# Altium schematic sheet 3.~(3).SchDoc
size 420 x 297 mm
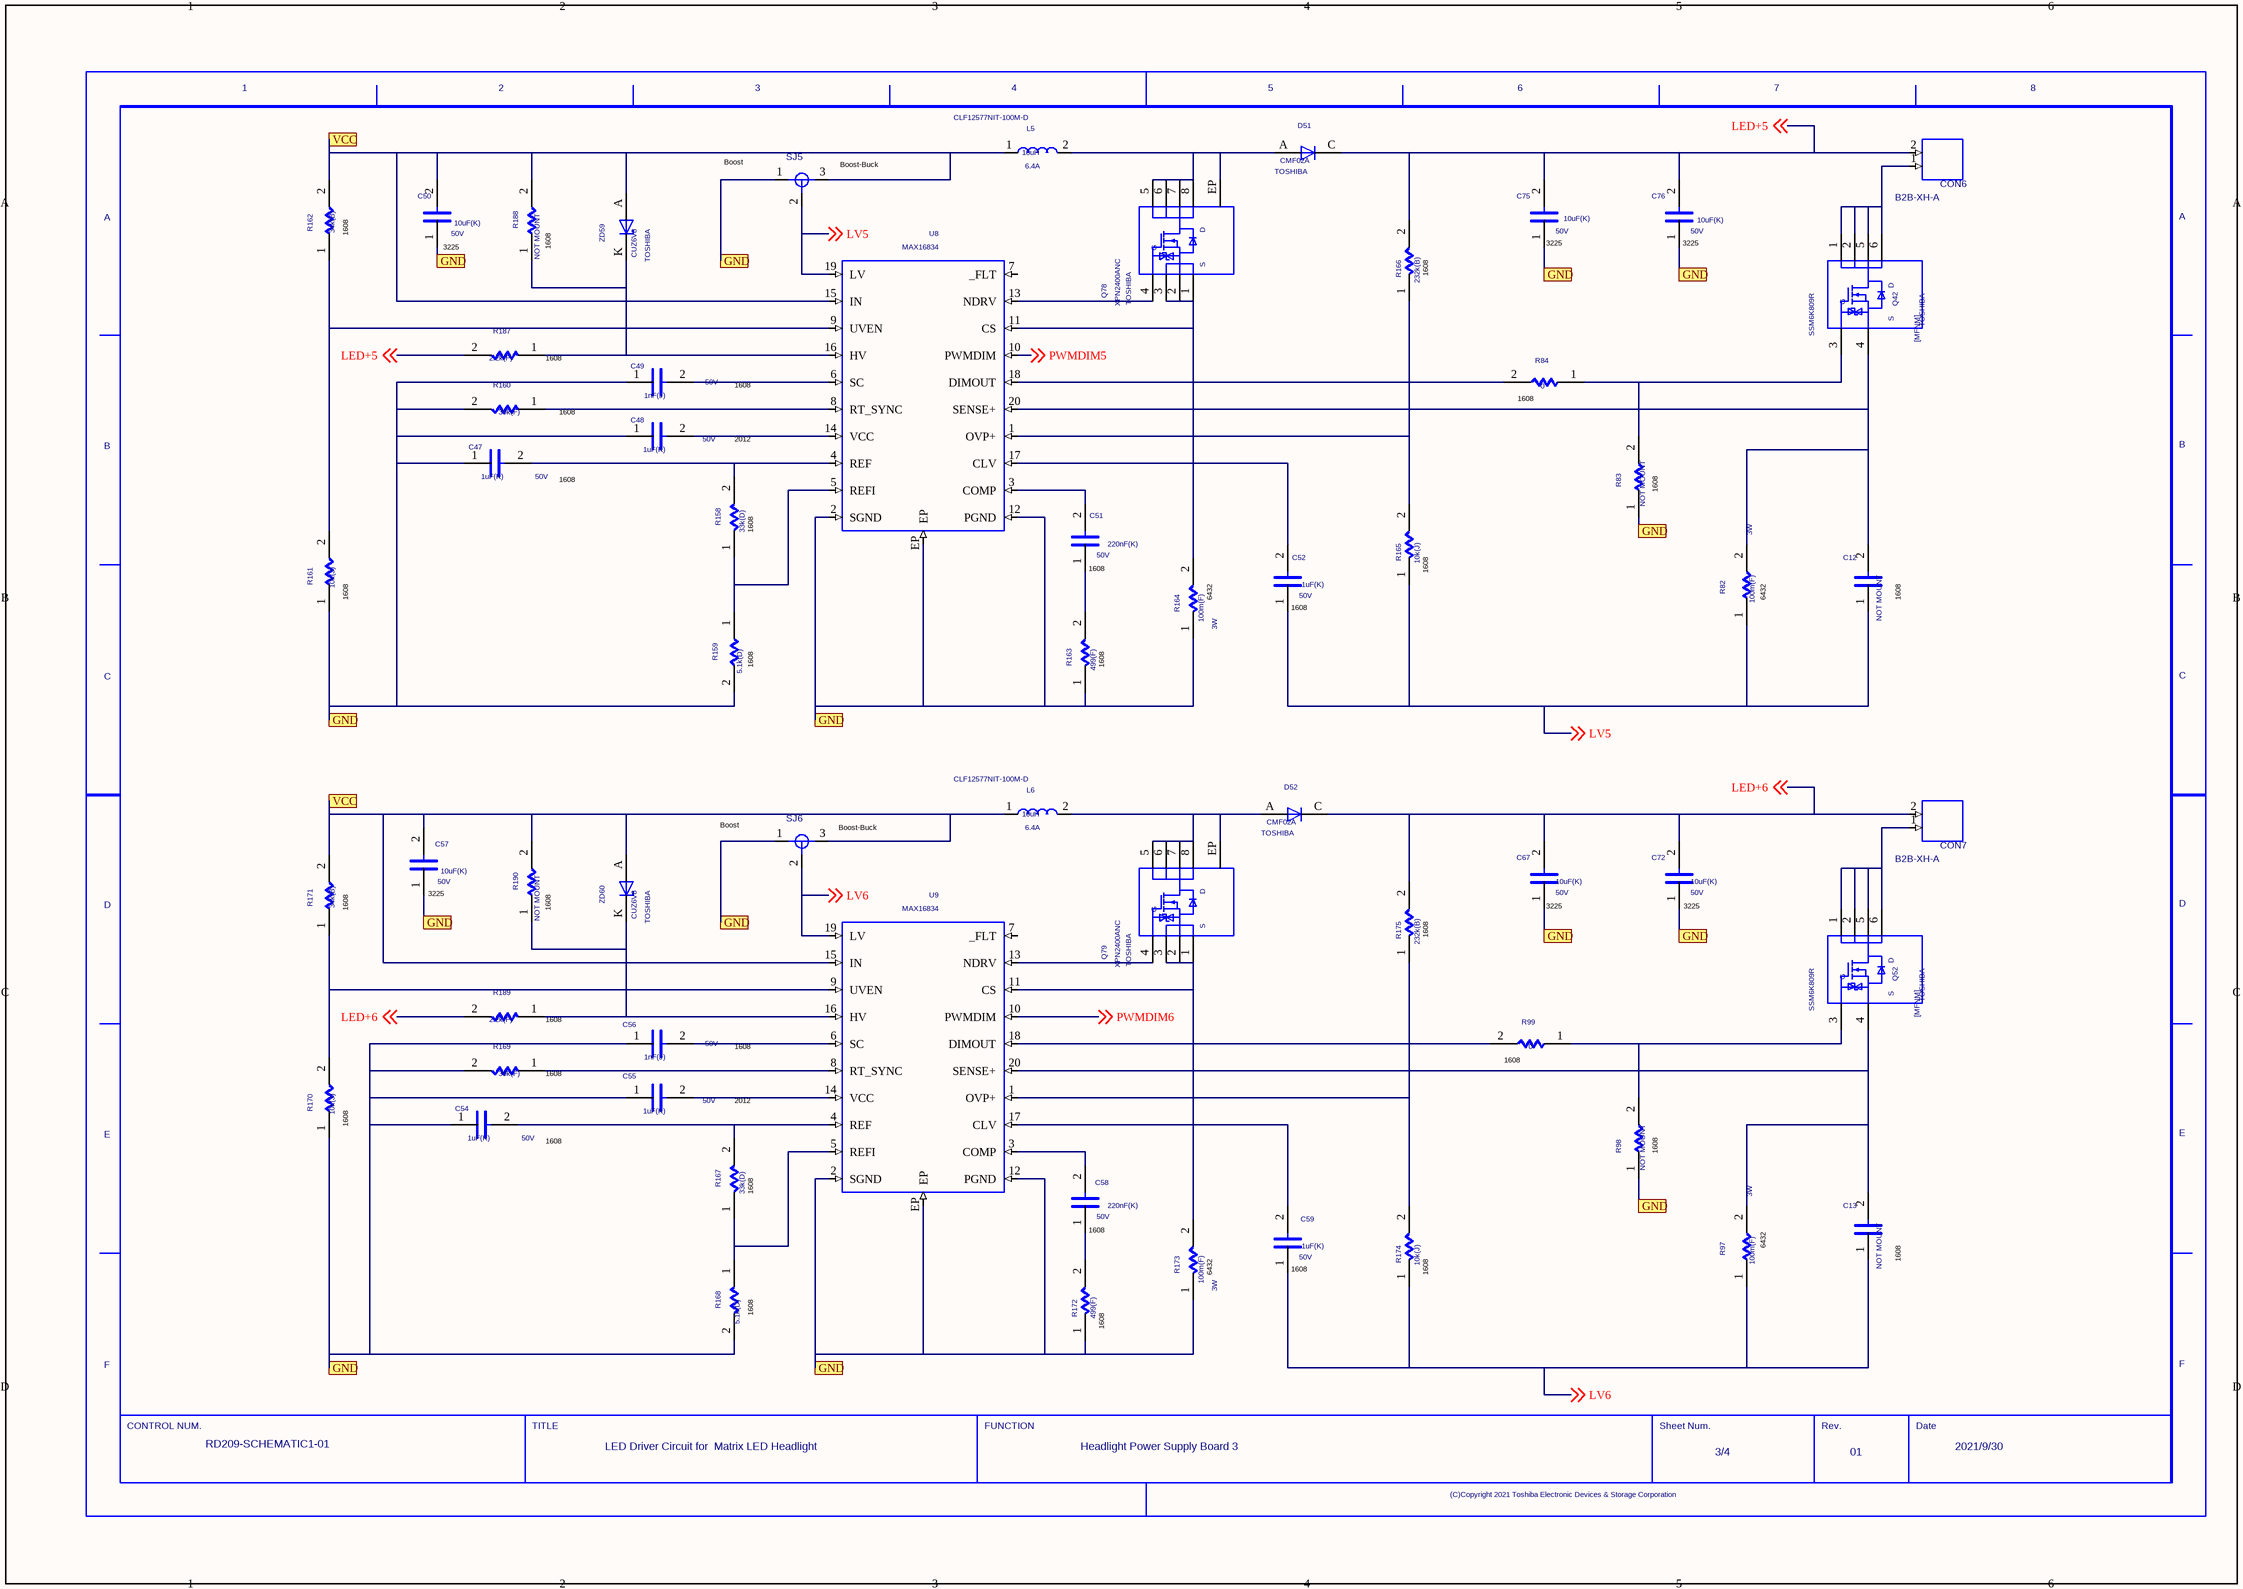
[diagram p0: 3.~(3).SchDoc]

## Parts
C12  NOTMOUNT: NOT MOUNT  (hidden comment: C)
C13  NOTMOUNT: NOT MOUNT  (hidden comment: C)
C47  VAL2: 50V  VAL1: 1uF(K)  (hidden comment: C)
C48  VAL2: 50V  VAL1: 1uF(K)  (hidden comment: C)
C49  VAL2: 50V  VAL1: 1nF(J)  (hidden comment: C)
C50  VAL2: 50V  VAL1: 10uF(K)  (hidden comment: C)
C51  VAL2: 50V  VAL1: 220nF(K)  (hidden comment: C)
C52  VAL2: 50V  VAL1: 1uF(K)  (hidden comment: C)
C54  VAL2: 50V  VAL1: 1uF(K)  (hidden comment: C)
C55  VAL2: 50V  VAL1: 1uF(K)  (hidden comment: C)
C56  VAL2: 50V  VAL1: 1nF(J)  (hidden comment: C)
C57  VAL2: 50V  VAL1: 10uF(K)  (hidden comment: C)
C58  VAL2: 50V  VAL1: 220nF(K)  (hidden comment: C)
C59  VAL2: 50V  VAL1: 1uF(K)  (hidden comment: C)
C67  VAL2: 50V  VAL1: 10uF(K)  (hidden comment: C)
C72  VAL2: 50V  VAL1: 10uF(K)  (hidden comment: C)
C75  VAL2: 50V  VAL1: 10uF(K)  (hidden comment: C)
C76  VAL2: 50V  VAL1: 10uF(K)  (hidden comment: C)
CON6  B2B-XH-A  [B2B-XH-A]
CON7  B2B-XH-A  [B2B-XH-A]
D51  USERCOMPTEXT3: TOSHIBA  VAL3: CMF02A  (hidden comment: D)
D52  USERCOMPTEXT3: TOSHIBA  VAL3: CMF02A  (hidden comment: D)
L5  VAL3: CLF12577NIT-100M-D  VAL2: 6.4A  VAL1: 10uH  (hidden comment: L)
L6  VAL3: CLF12577NIT-100M-D  VAL2: 6.4A  VAL1: 10uH  (hidden comment: L)
Q42  USERCOMPTEXT3: TOSHIBA  VAL3: SSM6K809R  (hidden comment: MFNM)
Q52  USERCOMPTEXT3: TOSHIBA  VAL3: SSM6K809R  (hidden comment: MFNM)
Q78  USERCOMPTEXT3: TOSHIBA  VAL3: XPN2400ANC  (hidden comment: MFNKR1)
Q79  USERCOMPTEXT3: TOSHIBA  VAL3: XPN2400ANC  (hidden comment: MFNKR1)
R82  VAL2: 3W  VAL1: 100m(F)  (hidden comment: R)
R83  NOTMOUNT: NOT MOUNT  (hidden comment: R)
R84  VAL1: 0  (hidden comment: R)
R97  VAL2: 3W  VAL1: 100m(F)  (hidden comment: R)
R98  NOTMOUNT: NOT MOUNT  (hidden comment: R)
R99  VAL1: 0  (hidden comment: R)
R158  VAL1: 33k(D)  (hidden comment: R)
R159  VAL1: 5.1k(D)  (hidden comment: R)
R160  VAL1: 39k(F)  (hidden comment: R)
R161  VAL1: 10k(J)  (hidden comment: R)
R162  VAL1: 34k(B)  (hidden comment: R)
R163  VAL1: 499(F)  (hidden comment: R)
R164  VAL2: 3W  VAL1: 100m(F)  (hidden comment: R)
R165  VAL1: 10k(J)  (hidden comment: R)
R166  VAL1: 232k(B)  (hidden comment: R)
R167  VAL1: 33k(D)  (hidden comment: R)
R168  VAL1: 5.1k(D)  (hidden comment: R)
R169  VAL1: 39k(F)  (hidden comment: R)
R170  VAL1: 10k(J)  (hidden comment: R)
R171  VAL1: 34k(B)  (hidden comment: R)
R172  VAL1: 499(F)  (hidden comment: R)
R173  VAL2: 3W  VAL1: 100m(F)  (hidden comment: R)
R174  VAL1: 10k(J)  (hidden comment: R)
R175  VAL1: 232k(B)  (hidden comment: R)
R187  VAL1: 2.2k(F)  (hidden comment: R)
R188  NOTMOUNT: NOT MOUNT  (hidden comment: R)
R189  VAL1: 2.2k(F)  (hidden comment: R)
R190  NOTMOUNT: NOT MOUNT  (hidden comment: R)
SJ5  SJ2W  (value not drawn)
SJ6  SJ2W  (value not drawn)
U8  MAX16834
U9  MAX16834
U?  DATE: 2021/9/30  REVISION: 01  DRAWINGNUMBER: RD209-SCHEMATIC1-01  FUNCTION: Headlight Power Supply Board 3  SHEETNUMBER: 3/4  TITLE: LED Driver Circuit for / Matrix LED Headlight  (hidden comment: WAKU_DEF100)
ZD59  USERCOMPTEXT3: TOSHIBA  VAL3: CUZ6V8  (hidden comment: ZD)
ZD60  USERCOMPTEXT3: TOSHIBA  VAL3: CUZ6V8  (hidden comment: ZD)

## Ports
GND, VCC

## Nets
GND: C47.1 C48.1 C49.1 C50.1 C54.1 C55.1 C56.1 C57.1 C67.1 C72.1 C75.1 C76.1 R83.1 R98.1 R159.2 R160.2 R161.1 R163.1 R164.1 R168.2 R169.2 R170.1 R172.1 R173.1 SJ5.1 SJ6.1 U8.2(SGND) U8.12(PGND) U8.EP U9.2(SGND) U9.12(PGND) U9.EP ; port GND
LED+5: C75.2 C76.2 CON6.2 D51.C R166.2 R187.2 ; off-sheet LED+5
LED+6: C67.2 C72.2 CON7.2 D52.C R175.2 R189.2 ; off-sheet LED+6
LV5: C12.1 C52.1 R82.1 R165.1 SJ5.2 U8.19(LV) ; off-sheet LV5
LV6: C13.1 C59.1 R97.1 R174.1 SJ6.2 U9.19(LV) ; off-sheet LV6
PWMDIM5: U8.10(PWMDIM) ; off-sheet PWMDIM5
PWMDIM6: U9.10(PWMDIM) ; off-sheet PWMDIM6
SIG719: C59.2 U9.17(CLV)
SIG721: R160.1 U8.8(RT_SYNC)
SIG722: C58.2 U9.3(COMP)
SIG723: Q79.1 Q79.2 Q79.3 R173.2 U9.11(CS)
SIG724: D52.A L6.2 Q79.5 Q79.6 Q79.7 Q79.8 Q79.EP
SIG727: CON7.1 Q52.1 Q52.2 Q52.5 Q52.6
SIG729: C48.2 U8.14(VCC)
SIG730: Q78.4 U8.13(NDRV)
SIG732: R158.1 R159.1 U8.5(REFI)
SIG733: C49.2 U8.6(SC)
SIG735: C51.2 U8.3(COMP)
SIG736: C52.2 U8.17(CLV)
SIG737: C47.2 R158.2 U8.4(REF)
SIG738: C13.2 Q52.4 R97.2 U9.20(SENSE+)
SIG740: Q78.1 Q78.2 Q78.3 R164.2 U8.11(CS)
SIG741: R187.1 R188.1 U8.16(HV) ZD59.K(C)
SIG743: CON6.1 Q42.1 Q42.2 Q42.5 Q42.6
SIG744: Q42.3 R83.2 R84.1
SIG745: C51.1 R163.2
SIG746: C58.1 R172.2
SIG748: R170.2 R171.1 U9.9(UVEN)
SIG749: Q79.4 U9.13(NDRV)
SIG750: C54.2 R167.2 U9.4(REF)
SIG753: C55.2 U9.14(VCC)
SIG754: C12.2 Q42.4 R82.2 U8.20(SENSE+)
SIG755: D51.A L5.2 Q78.5 Q78.6 Q78.7 Q78.8 Q78.EP
SIG756: R167.1 R168.1 U9.5(REFI)
SIG760: R189.1 R190.1 U9.16(HV) ZD60.K(C)
SIG761: R84.2 U8.18(DIMOUT)
SIG763: R174.2 R175.1 U9.1(OVP+)
SIG764: R165.2 R166.1 U8.1(OVP+)
SIG765: C56.2 U9.6(SC)
SIG766: R99.2 U9.18(DIMOUT)
SIG767: R169.1 U9.8(RT_SYNC)
SIG768: R161.2 R162.1 U8.9(UVEN)
SIG770: Q52.3 R98.2 R99.1
VCC: C50.2 C57.2 L5.1 L6.1 R162.2 R171.2 R188.2 R190.2 SJ5.3 SJ6.3 U8.15(IN) U9.15(IN) ZD59.A ZD60.A ; port VCC

Not connected (* = marked no-connect by the designer): U8 7(_FLT); U9 7(_FLT)

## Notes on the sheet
- (near SJ5) Boost
- (near SJ5) Boost-Buck
- (near R162) 1608
- (near C50) 3225
- (near R188) 1608
- (near C75) 3225
- (near C76) 3225
- (near R166) 1608
- (near R187) 1608
- 1608
- (near R160) 1608
- 2012
- (near R84) 1608
- (near R158) 1608
- (near R83) 1608
- (near R161) 1608
- (near C51) 1608
- (near R164) 6432
- (near R165) 1608
- (near R82) 6432
- (near C12) 1608
- (near R159) 1608
- (near R163) 1608
- (near C52) 1608
- (near SJ6) Boost
- (near SJ6) Boost-Buck
- (near R171) 1608
- (near C57) 3225
- (near R190) 1608
- (near R175) 1608
- (near C67) 3225
- (near C72) 3225
- (near R189) 1608
- (near R99) 1608
- (near R170) 1608
- (near R169) 1608
- (near R167) 1608
- (near R98) 1608
- (near C58) 1608
- (near R173) 6432
- (near C59) 1608
- (near R174) 1608
- (near R97) 6432
- (near C13) 1608
- (near R168) 1608
- (near R172) 1608

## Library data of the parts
C12 = C: TIME: 17:22:43; UPDATEUSER: t5459927; SAVECOUNT: 1; OriginalSymbolOrigin: (2540,7620); INSTANCENAME: cmp123; CDBNAME: C0603K
C13 = C: TIME: 17:22:43; UPDATEUSER: t5459927; SAVECOUNT: 1; OriginalSymbolOrigin: (2540,7620); INSTANCENAME: cmp180; CDBNAME: C0603K
C47 = C: TIME: 17:22:43; UPDATEUSER: t5459927; SAVECOUNT: 1; OriginalSymbolOrigin: (2540,7620); INSTANCENAME: cmp124; CDBNAME: C0603K_3
C48 = C: TIME: 17:22:43; UPDATEUSER: t5459927; SAVECOUNT: 1; OriginalSymbolOrigin: (2540,7620); INSTANCENAME: cmp113; CDBNAME: C0805K_1
C49 = C: TIME: 17:22:43; UPDATEUSER: t5459927; SAVECOUNT: 1; OriginalSymbolOrigin: (2540,7620); INSTANCENAME: cmp171; CDBNAME: C0603K_1
C50 = C: TIME: 17:22:43; UPDATEUSER: t5459927; SAVECOUNT: 1; OriginalSymbolOrigin: (2540,7620); INSTANCENAME: cmp149; CDBNAME: C1210K
C51 = C: TIME: 17:22:43; UPDATEUSER: t5459927; SAVECOUNT: 1; OriginalSymbolOrigin: (2540,7620); INSTANCENAME: cmp114; CDBNAME: C0603K_4
C52 = C: TIME: 17:22:43; UPDATEUSER: t5459927; SAVECOUNT: 1; OriginalSymbolOrigin: (2540,7620); INSTANCENAME: cmp167; CDBNAME: C0603K_3
C54 = C: TIME: 17:22:43; UPDATEUSER: t5459927; SAVECOUNT: 1; OriginalSymbolOrigin: (2540,7620); INSTANCENAME: cmp144; CDBNAME: C0603K_3
C55 = C: TIME: 17:22:43; UPDATEUSER: t5459927; SAVECOUNT: 1; OriginalSymbolOrigin: (2540,7620); INSTANCENAME: cmp147; CDBNAME: C0805K_1
C56 = C: TIME: 17:22:43; UPDATEUSER: t5459927; SAVECOUNT: 1; OriginalSymbolOrigin: (2540,7620); INSTANCENAME: cmp153; CDBNAME: C0603K_1
C57 = C: TIME: 17:22:43; UPDATEUSER: t5459927; SAVECOUNT: 1; OriginalSymbolOrigin: (2540,7620); INSTANCENAME: cmp166; CDBNAME: C1210K
C58 = C: TIME: 17:22:43; UPDATEUSER: t5459927; SAVECOUNT: 1; OriginalSymbolOrigin: (2540,7620); INSTANCENAME: cmp119; CDBNAME: C0603K_4
C59 = C: TIME: 17:22:43; UPDATEUSER: t5459927; SAVECOUNT: 1; OriginalSymbolOrigin: (2540,7620); INSTANCENAME: cmp148; CDBNAME: C0603K_3
C67 = C: TIME: 17:22:43; UPDATEUSER: t5459927; SAVECOUNT: 1; OriginalSymbolOrigin: (2540,7620); INSTANCENAME: cmp111; CDBNAME: C1210K
C72 = C: TIME: 17:22:43; UPDATEUSER: t5459927; SAVECOUNT: 1; OriginalSymbolOrigin: (2540,7620); INSTANCENAME: cmp175; CDBNAME: C1210K
C75 = C: TIME: 17:22:43; UPDATEUSER: t5459927; SAVECOUNT: 1; OriginalSymbolOrigin: (2540,7620); INSTANCENAME: cmp157; CDBNAME: C1210K
C76 = C: TIME: 17:22:43; UPDATEUSER: t5459927; SAVECOUNT: 1; OriginalSymbolOrigin: (2540,7620); INSTANCENAME: cmp173; CDBNAME: C1210K
CON6 CON7 = B2B_XH_A: SAVECOUNT: 1; COMP: B2_BX_HA; UPDATEUSER: t5459927; UPDATETIME: 17:22:42; OriginalSymbolOrigin: (0,0); COMPONENTNAME: CON; INSTANCENAME: INS9160
D51 D52 = D: SAVEAREA0: -225,-91,12804,7836; SAVECOUNT: 3; TIME: 14:49:55; UPDATEUSER: 19870035; UPDATETIME: 14:20:16; OriginalSymbolOrigin: (5080,5080); CDBNAME: M-FLAT
L5 = L: COMP: CLF12577NI_D; TIME: 17:22:43; UPDATEUSER: t5459927; SAVECOUNT: 1; OriginalSymbolOrigin: (2540,5080); INSTANCENAME: cmp146; CDBNAME: CLF12577NI-D
L6 = L: COMP: CLF12577NI_D; TIME: 17:22:43; UPDATEUSER: t5459927; SAVECOUNT: 1; OriginalSymbolOrigin: (2540,5080); INSTANCENAME: cmp190; CDBNAME: CLF12577NI-D
Q42 = MFNM: TIME: 17:22:43; SAVECOUNT: 1; SAVEAREA0: -6986,-322,29385,23602; UPDATEUSER: t5459927; OriginalSymbolOrigin: (5080,20320); COMPONENTNAME: Q; INSTANCENAME: cmp117; CDBNAME: TSOP6F
Q52 = MFNM: TIME: 17:22:43; SAVECOUNT: 1; SAVEAREA0: -6986,-322,29385,23602; UPDATEUSER: t5459927; OriginalSymbolOrigin: (5080,20320); COMPONENTNAME: Q; INSTANCENAME: cmp187; CDBNAME: TSOP6F
Q78 Q79 = MFNKR1: TIME: 17:22:43; SAVECOUNT: 2; SAVEAREA0: -5755,-491,27794,24105; COMP: TSON_ADVANCE_WF_1; UPDATETIME: 09:26:31; UPDATEUSER: t5459927; OriginalSymbolOrigin: (5080,20320); COMPONENTNAME: Q
R82 = R: TIME: 17:22:43; UPDATEUSER: t5459927; SAVECOUNT: 1; OriginalSymbolOrigin: (5080,5080); INSTANCENAME: cmp162; CDBNAME: R2512
R83 = R: TIME: 17:22:43; UPDATEUSER: t5459927; SAVECOUNT: 1; OriginalSymbolOrigin: (5080,5080); INSTANCENAME: cmp181; CDBNAME: R0603
R84 = R: TIME: 17:22:43; UPDATEUSER: t5459927; SAVECOUNT: 1; OriginalSymbolOrigin: (5080,5080); INSTANCENAME: cmp128; CDBNAME: R0603_7
R97 = R: TIME: 17:22:43; UPDATEUSER: t5459927; SAVECOUNT: 1; OriginalSymbolOrigin: (5080,5080); INSTANCENAME: cmp169; CDBNAME: R2512
R98 = R: TIME: 17:22:43; UPDATEUSER: t5459927; SAVECOUNT: 1; OriginalSymbolOrigin: (5080,5080); INSTANCENAME: cmp125; CDBNAME: R0603
R99 = R: TIME: 17:22:43; UPDATEUSER: t5459927; SAVECOUNT: 1; OriginalSymbolOrigin: (5080,5080); INSTANCENAME: cmp191; CDBNAME: R0603_7
R158 = R#1: TIME: 17:22:43; UPDATEUSER: t5459927; SAVECOUNT: 1; OriginalSymbolOrigin: (5080,5080); CaptureCellPackProp: R##1; VAL2: 100mW; INSTANCENAME: cmp155; CDBNAME: R0603_11
R159 = R: TIME: 17:22:43; UPDATEUSER: t5459927; SAVECOUNT: 1; OriginalSymbolOrigin: (5080,5080); VAL2: 100mW; INSTANCENAME: cmp145; CDBNAME: R0603_10
R160 = R: TIME: 17:22:43; UPDATEUSER: t5459927; SAVECOUNT: 1; OriginalSymbolOrigin: (5080,5080); VAL2: 100mW; INSTANCENAME: cmp163; CDBNAME: R0603_8
R161 = R: TIME: 17:22:43; UPDATEUSER: t5459927; SAVECOUNT: 1; OriginalSymbolOrigin: (5080,5080); VAL2: 100mW; INSTANCENAME: cmp122; CDBNAME: R0603_6
R162 = R: TIME: 17:22:43; UPDATEUSER: t5459927; SAVECOUNT: 1; OriginalSymbolOrigin: (5080,5080); VAL2: 100mW; INSTANCENAME: cmp136; CDBNAME: R0603_1
R163 = R: TIME: 17:22:43; UPDATEUSER: t5459927; SAVECOUNT: 1; OriginalSymbolOrigin: (5080,5080); VAL2: 125mW; INSTANCENAME: cmp135; CDBNAME: R0603_12
R164 = R: TIME: 17:22:43; UPDATEUSER: t5459927; SAVECOUNT: 1; OriginalSymbolOrigin: (5080,5080); INSTANCENAME: cmp164; CDBNAME: R2512
R165 = R: TIME: 17:22:43; UPDATEUSER: t5459927; SAVECOUNT: 1; OriginalSymbolOrigin: (5080,5080); VAL2: 100mW; INSTANCENAME: cmp139; CDBNAME: R0603_6
R166 = R: TIME: 17:22:43; UPDATEUSER: t5459927; SAVECOUNT: 1; OriginalSymbolOrigin: (5080,5080); VAL2: 63mW; INSTANCENAME: cmp168; CDBNAME: R0603_9
R167 = R#1: TIME: 17:22:43; UPDATEUSER: t5459927; SAVECOUNT: 1; OriginalSymbolOrigin: (5080,5080); CaptureCellPackProp: R##1; VAL2: 100mW; INSTANCENAME: cmp158; CDBNAME: R0603_11
R168 = R: TIME: 17:22:43; UPDATEUSER: t5459927; SAVECOUNT: 1; OriginalSymbolOrigin: (5080,5080); VAL2: 100mW; INSTANCENAME: cmp179; CDBNAME: R0603_10
R169 = R: TIME: 17:22:43; UPDATEUSER: t5459927; SAVECOUNT: 1; OriginalSymbolOrigin: (5080,5080); VAL2: 100mW; INSTANCENAME: cmp127; CDBNAME: R0603_8
R170 = R: TIME: 17:22:43; UPDATEUSER: t5459927; SAVECOUNT: 1; OriginalSymbolOrigin: (5080,5080); VAL2: 100mW; INSTANCENAME: cmp131; CDBNAME: R0603_6
R171 = R: TIME: 17:22:43; UPDATEUSER: t5459927; SAVECOUNT: 1; OriginalSymbolOrigin: (5080,5080); VAL2: 100mW; INSTANCENAME: cmp116; CDBNAME: R0603_1
R172 = R: TIME: 17:22:43; UPDATEUSER: t5459927; SAVECOUNT: 1; OriginalSymbolOrigin: (5080,5080); VAL2: 125mW; INSTANCENAME: cmp176; CDBNAME: R0603_12
R173 = R: TIME: 17:22:43; UPDATEUSER: t5459927; SAVECOUNT: 1; OriginalSymbolOrigin: (5080,5080); INSTANCENAME: cmp115; CDBNAME: R2512
R174 = R: TIME: 17:22:43; UPDATEUSER: t5459927; SAVECOUNT: 1; OriginalSymbolOrigin: (5080,5080); VAL2: 100mW; INSTANCENAME: cmp134; CDBNAME: R0603_6
R175 = R: TIME: 17:22:43; UPDATEUSER: t5459927; SAVECOUNT: 1; OriginalSymbolOrigin: (5080,5080); VAL2: 63mW; INSTANCENAME: cmp185; CDBNAME: R0603_9
R187 = R: TIME: 17:22:43; UPDATEUSER: t5459927; SAVECOUNT: 1; OriginalSymbolOrigin: (5080,5080); VAL2: 100mW; INSTANCENAME: cmp109; CDBNAME: R0603_2
R188 = R: TIME: 17:22:43; UPDATEUSER: t5459927; SAVECOUNT: 1; OriginalSymbolOrigin: (5080,5080); INSTANCENAME: cmp137; CDBNAME: R0603
R189 = R: TIME: 17:22:43; UPDATEUSER: t5459927; SAVECOUNT: 1; OriginalSymbolOrigin: (5080,5080); VAL2: 100mW; INSTANCENAME: cmp189; CDBNAME: R0603_2
R190 = R: TIME: 17:22:43; UPDATEUSER: t5459927; SAVECOUNT: 1; OriginalSymbolOrigin: (5080,5080); INSTANCENAME: cmp156; CDBNAME: R0603
SJ5 = SJ2W: SAVECOUNT: 1; COMP: SJ_2; SAVEAREA0: -15743,-4510,23437,11881; UPDATEUSER: t5459927; UPDATETIME: 17:22:42; OriginalSymbolOrigin: (2540,7620); COMPONENTNAME: SJ; INSTANCENAME: cmp132
SJ6 = SJ2W: SAVECOUNT: 1; COMP: SJ_2; SAVEAREA0: -15743,-4510,23437,11881; UPDATEUSER: t5459927; UPDATETIME: 17:22:42; OriginalSymbolOrigin: (2540,7620); COMPONENTNAME: SJ; INSTANCENAME: cmp196
U8 U9 = MAX16834: SAVECOUNT: 1; COMP: 20-TQFN; SAVEAREA0: -47937,-54417,76568,2975; UPDATEUSER: t5459927; UPDATETIME: 17:22:42; OriginalSymbolOrigin: (0,0); COMPONENTNAME: IC; INSTANCENAME: cmp580
U? = WAKU_DEF100: PLOTTIME: HH:MM; SAVEAREA0: 147884,-66467,487065,89883; TIME: 14:30:25; UPDATEUSER: t5459927; UPDATETIME: 12:50:54; SAVECOUNT: 7; OriginalSymbolOrigin: (10160,284480)
ZD59 = ZD: TIME: 17:22:43; SAVECOUNT: 1; SAVEAREA0: -4630,-153,17114,13055; UPDATEUSER: t5459927; OriginalSymbolOrigin: (5080,5080); INSTANCENAME: cmp183; CDBNAME: USC
ZD60 = ZD: TIME: 17:22:43; SAVECOUNT: 1; SAVEAREA0: -4630,-153,17114,13055; UPDATEUSER: t5459927; OriginalSymbolOrigin: (5080,5080); INSTANCENAME: cmp192; CDBNAME: USC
